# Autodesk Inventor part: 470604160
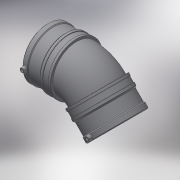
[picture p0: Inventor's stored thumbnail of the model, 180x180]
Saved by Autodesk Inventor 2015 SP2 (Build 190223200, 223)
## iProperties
Created: 2017-06
Part Number: 470604160
Material: Generic
Description: PLASSON WASTEWATER 45° ELBOW 160-160 LIGHTFIT
Document SubType Name: Modeling
Designer: KIM
Mass: 12693.1 g
Surface Area: 10598.3 cm^2
Volume: 12693.1 cm^3
Density: 1 g/cm^3
Appearance: Default
Author: KIM
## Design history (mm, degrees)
derived "470604.ipt"
feature "Solid1::470604.ipt"
tag "TaggingFeature1"
body "Solid1"
other parameters: "d14" = 17.6296, "d19" = 3.52592, "d20" = 168 deg, "d22" = 189.14, "d23" = 193, "d24" = 183.4658, "d25" = 135 deg, "d29" = 106, "d43" = 135 deg, "d45" = 13, "d47" = 9.75, "d48" = 189.14, "d49" = 193, "d50" = 0.965, "d51" = 91.7329, "d52" = 135 deg, "d53" = 325, "d54" = 21.56, "d55" = 107.8, "d56" = 152, "d57" = 68.6, "d58" = 106, "d59" = 15, "d61" = 5 deg, "d63" = 4, "d64" = 14, "d65" = 0, "d67" = 135 deg, "d69" = 176, "d71" = 98, "d72" = 0, "d73" = 98, "d74" = 0, "d75" = 3, "d76" = 0, "L_" = 325, "L_1" = 98, "D_" = 193, "A_" = 106, "d_2" = 12
